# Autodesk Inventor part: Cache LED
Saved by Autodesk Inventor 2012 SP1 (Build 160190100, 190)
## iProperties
Created: 2014-12
Part Number: Cache LED
Material: Default
Document SubType Name: Modeling
Designer: Bruno
Density: 1 g/cm^3
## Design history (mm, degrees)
node "Cache LED1"
node "Cache LED"
node "Base1"
